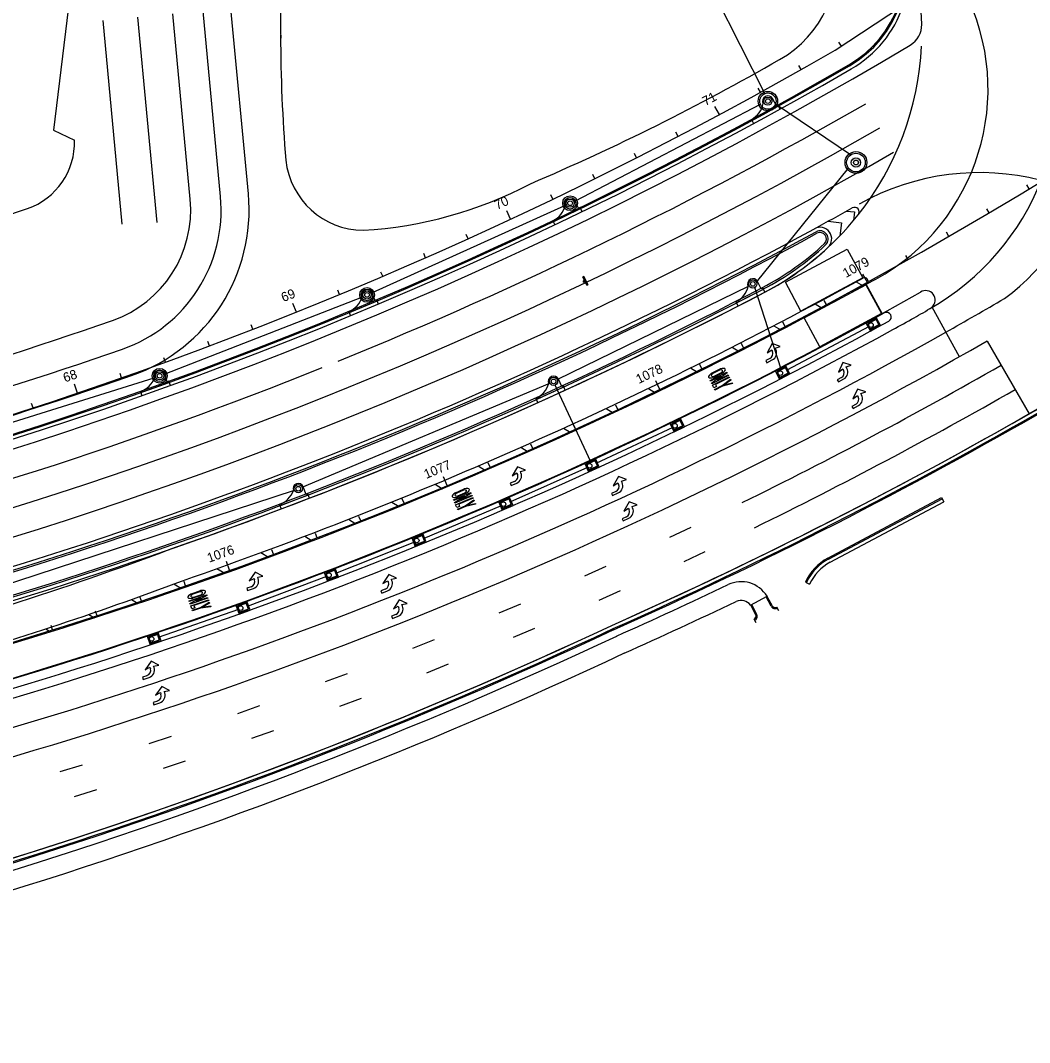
# Model space of a CAD drawing. Extents: x 468143 to 491361, y 1438528 to 1468730.
# Drawn here: x 489702.4 to 490134.6, y 1466592.5 to 1467030.2 of the extents above; entities that cross this region are included whole.
import ezdxf

# ---------------------------------------------------------------- set-up
doc = ezdxf.new("R2010")
doc.units = 0
doc.layers.add('Default', color=7, linetype='Continuous')
doc.layers.add('Xreference_dp', color=7, linetype='Continuous')

# ---------------------------------------------------------------- blocks, each defined once
blk = doc.blocks.new('POINT_DISPLAY')
at = {"layer": 'Default'}
blk.add_line((0, 0), (0, 0), dxfattribs=at)
blk = doc.blocks.new('InltCurb1_35')
at = {"layer": 'Default'}
for p, q in [((2.25, 2), (2.25, 5.5)), ((-10, 2), (-10, 0)), ((-10, 1.5), (3, 1.5)), ((3, 2), (2.25, 2)), ((3, 0), (3, 2))]:
    blk.add_line(p, q, dxfattribs=at)
for radius in [1.75, 1]:
    blk.add_circle((0, 5.5), radius, dxfattribs=at)
for centre, radius, start, end in [((-9.85, 12), 10, 269.1432, 319.4677), ((0, 5.5), 2.25, 0, 180)]:
    blk.add_arc(centre, radius, start, end, dxfattribs=at)
for p in [(-1.75, 5.5), (-1.75, 5.5), (-1.62, 4.84), (-1.6, 6.2), (-1.22, 6.76), (-0.66, 7.12), (0, 7.75), (0, 7.25), (0, 7.25), (0, 5.5), (0, 5.5), (0.7, 7.1), (1.26, 6.72), (1.6, 4.8), (1.62, 6.16), (1.75, 5.5), (1.75, 5.5), (-1.26, 4.28), (-0.7, 3.9), (0, 3.75), (0, 3.75), (0, 0), (0, 0), (0.66, 3.88), (1.22, 4.24)]:
    blk.add_blockref('POINT_DISPLAY', p, dxfattribs=at)
blk = doc.blocks.new('InltCurb7_40')
at = {"layer": 'Default'}
for p, q in [((2.5, 4), (-2.5, 4)), ((-2.5, 4), (-2.5, 0)), ((2.5, 3.25), (-2.5, 3.25)), ((-2.5, 0.75), (2.5, 0.75)), ((-2.5, 0), (2.5, 0)), ((2.5, 0), (2.5, 4))]:
    blk.add_line(p, q, dxfattribs=at)
blk.add_lwpolyline([(-2, 0.5), (2, 0.5), (2, 3.5), (-2, 3.5)], close=True, dxfattribs=at)
blk.add_circle((-1.04, 2.19), 1, dxfattribs=at)
for p in [(-2, 3.5), (-2, 2), (-2, 2), (-2, 0.5), (0, 4), (0, 3.5), (0, 3.5), (0, 2), (0, 2), (0, 0.5), (0, 0.5), (0, 0), (0, 0), (2, 3.5), (2, 2), (2, 2), (2, 0.5)]:
    blk.add_blockref('POINT_DISPLAY', p, dxfattribs=at)
blk = doc.blocks.new('MHCover2')
at = {"layer": 'Default'}
for radius in [2, 1.06, 1]:
    blk.add_circle((0, 0), radius, dxfattribs=at)
for p in [(-2, 0), (-2, 0), (-1.83, 0.81), (-1.39, 1.43), (-0.75, 1.85), (0, 2.5), (0, 2), (0, 2), (0, 0), (0, 0), (0, 0), (0.81, 1.83), (1.43, 1.39), (1.85, 0.75), (2, 0), (2, 0), (-1.85, -0.75), (-1.43, -1.39), (-0.81, -1.83), (0, -2), (0, -2), (0, -2.5), (0.75, -1.85), (1.39, -1.43), (1.83, -0.81)]:
    blk.add_blockref('POINT_DISPLAY', p, dxfattribs=at)
blk = doc.blocks.new('JBottom80Dia')
at = {"layer": 'Default'}
for radius in [4.67, 4, 4]:
    blk.add_circle((0, 0), radius, dxfattribs=at)
for p in [(-3.66, 1.61), (-2.79, 2.87), (-1.5, 3.71), (0, 4), (0, 4), (0, 4), (0, 0), (0, 0), (0, 0), (1.61, 3.66), (2.87, 2.79), (3.71, 1.5), (4, 0), (4, 0), (-4, 0), (-4, 0), (-3.71, -1.5), (-2.87, -2.79), (-1.61, -3.66), (0, -4), (0, -4), (0, -4), (1.5, -3.71), (2.79, -2.87), (3.66, -1.61)]:
    blk.add_blockref('POINT_DISPLAY', p, dxfattribs=at)
blk = doc.blocks.new('JBottom50Dia')
at = {"layer": 'Default'}
for radius in [3.17, 2.5, 2.5]:
    blk.add_circle((0, 0), radius, dxfattribs=at)
for p in [(-2.29, 1.01), (-1.74, 1.79), (-0.94, 2.32), (0, 2.5), (0, 2.5), (0, 2.5), (0, 0), (0, 0), (0, 0), (1.01, 2.29), (1.79, 1.74), (2.32, 0.94), (2.5, 0), (2.5, 0), (-2.5, 0), (-2.5, 0), (-2.32, -0.94), (-1.79, -1.74), (-1.01, -2.29), (0, -2.5), (0, -2.5), (0, -2.5), (0.94, -2.32), (1.74, -1.79), (2.29, -1.01)]:
    blk.add_blockref('POINT_DISPLAY', p, dxfattribs=at)
blk = doc.blocks.new('JBottom70Dia')
at = {"layer": 'Default'}
for radius in [4.17, 3.5, 3.5]:
    blk.add_circle((0, 0), radius, dxfattribs=at)
for p in [(-3.5, 0), (-3.5, 0), (-3.2, 1.41), (-2.44, 2.51), (-1.32, 3.24), (0, 3.5), (0, 3.5), (0, 3.5), (0, 0), (0, 0), (0, 0), (1.41, 3.2), (2.51, 2.44), (3.24, 1.32), (-3.24, -1.32), (-2.51, -2.44), (-1.41, -3.2), (0, -3.5), (0, -3.5), (0, -3.5), (1.32, -3.24), (2.44, -2.51), (3.2, -1.41), (3.5, 0), (3.5, 0)]:
    blk.add_blockref('POINT_DISPLAY', p, dxfattribs=at)
blk = doc.blocks.new('DALeftTurn_1')
at = {"layer": 'Default'}
for points in [[(5.67, 3.17), (2, 0.5), (4.33, 0.83), (4.33, 0.17)], [(6, 0.17), (6, 0.83), (8.25, 0.5), (5.67, 3.17)], [(2, -2.17), (0, -2.17), (0, -3.17), (2.67, -3.17)]]:
    blk.add_lwpolyline(points, dxfattribs=at)
for centre, radius in [((2, 0.17), 2.33), ((2.67, 0.17), 3.33)]:
    blk.add_arc(centre, radius, 270, 0, dxfattribs=at)
blk = doc.blocks.new('TG')
at = {"layer": 'Default'}
for p, q in [((0.048, -0.011), (-0.048, -0.011)), ((-0.048, -0.011), (-0.048, -0.023)), ((-0.048, -0.023), (0.048, -0.023)), ((0.048, -0.023), (0.048, -0.011))]:
    blk.add_line(p, q, dxfattribs=at)
blk.add_lwpolyline([(-0.048, -0.011), (0.048, -0.011), (0.048, -0.023), (-0.048, -0.023)], close=True, dxfattribs=at)
for start, end in [(0, 180), (180, 0)]:
    blk.add_arc((0, 0), 0.00607, start, end, dxfattribs=at)
blk = doc.blocks.new('ONLY_5')
at = {"layer": 'Default'}
for p, q in [((1.94, 3.96), (6.06, 3.96)), ((6.06, 1.96), (1.94, 1.96)), ((5.6, 3.63), (2.4, 3.63)), ((2.4, 2.29), (5.6, 2.29))]:
    blk.add_line(p, q, dxfattribs=at)
for points in [[(0, -0.12), (0, 0.21), (5, 1.13), (0, 1.13), (0, 1.46), (8, 1.46), (8, 1.13), (2.9, 0.21), (8, 0.21), (8, -0.12), (0, -0.12)], [(1.33, -2.12), (0, -2.12), (0, -0.79), (8, -0.79), (8, -1.12), (1.33, -1.12), (1.33, -2.12)], [(8, -3.96), (3.67, -3.12), (0, -3.12), (0, -2.79), (3.67, -2.79), (8, -1.96), (8, -2.3), (4.57, -2.96), (8, -3.62), (8, -3.96)]]:
    blk.add_lwpolyline(points, dxfattribs=at)
for major_axis, ratio, start_param, end_param in [((4, 0), 0.291667, 2.111896, 4.171289), ((2.67, 0), 0.3125, 2.214297, 4.068888), ((2.67, 0), 0.3125, 5.35589, 7.210481), ((4, 0), 0.291667, 5.253489, 7.312882)]:
    blk.add_ellipse((4, 2.96), major_axis=major_axis, ratio=ratio, start_param=start_param, end_param=end_param, dxfattribs=at)

msp = doc.modelspace()

# ---------------------------------------------------------------- linework, layer by layer
at = {"layer": 'Xreference_dp'}
for p, q in [((490051.34, 1467017.44), (490235.32, 1467139.02)), ((490021.16, 1466998.87), (489996.32, 1467047.97)), ((489800.04, 1466955.98), (489792.58, 1467035.34)), ((489800.04, 1466955.98), (489792.58, 1467035.34)), ((489761.02, 1466943.73), (489752.75, 1467031.6)), ((489761.02, 1466943.73), (489752.75, 1467031.6)), ((489775.15, 1466953.64), (489767.69, 1467033)), ((489775.15, 1466953.64), (489767.69, 1467033)), ((489788.09, 1466954.85), (489780.63, 1467034.22)), ((489788.09, 1466954.85), (489780.63, 1467034.22)), ((489746.02, 1466942.95), (489737.82, 1467030.19)), ((489746.02, 1466942.95), (489737.82, 1467030.19)), ((490054.07, 1467019.24), (490052.97, 1467020.91)), ((490036.81, 1467009.15), (490035.83, 1467010.89)), ((490019.34, 1466999.42), (490018.37, 1467001.17)), ((489940.15, 1466952.91), (490019.29, 1466994.29)), ((490001.76, 1466989.88), (489999.87, 1466993.4)), ((490057.89, 1466972.6), (490025.74, 1466994.28)), ((489984.08, 1466980.53), (489983.15, 1466982.31)), ((489966.3, 1466971.38), (489965.39, 1466973.16)), ((490017.64, 1466918.18), (490057, 1466967.01)), ((489948.41, 1466962.43), (489947.53, 1466964.22)), ((490134.43, 1466958.1), (490133.4, 1466959.81)), ((489930.43, 1466953.67), (489929.57, 1466955.47)), ((489853.18, 1466913.64), (489935.54, 1466950.97)), ((489912.36, 1466945.11), (489910.66, 1466948.73)), ((490117.27, 1466947.83), (490116.25, 1466949.55)), ((490100, 1466937.74), (490099, 1466939.47)), ((489894.19, 1466936.75), (489893.36, 1466938.57)), ((489875.93, 1466928.59), (489875.12, 1466930.42)), ((490082.63, 1466927.83), (490081.65, 1466929.57)), ((489857.58, 1466920.63), (489856.79, 1466922.47)), ((490065.16, 1466918.1), (490063.23, 1466921.61)), ((490060.39, 1466918.34), (490063.35, 1466916.54)), ((490071.48, 1466904.74), (490064.62, 1466917.23)), ((489839.14, 1466912.88), (489838.38, 1466914.73)), ((489932.34, 1466876.39), (490014.53, 1466916.57)), ((490028.14, 1466880.81), (490016.89, 1466915.82)), ((489764.41, 1466878.88), (489848.57, 1466911.7)), ((489820.62, 1466905.33), (489819.13, 1466909.04)), ((490042.77, 1466908.82), (490045.76, 1466907.01)), ((490047.58, 1466908.56), (490046.64, 1466910.32)), ((490104.53, 1466886.1), (490092.83, 1466907.41)), ((489802.02, 1466897.98), (489801.3, 1466899.85)), ((490025.06, 1466899.49), (490028.06, 1466897.67)), ((490029.91, 1466899.2), (490028.98, 1466900.97)), ((490065.9, 1466899.13), (490030.61, 1466880.4)), ((489783.34, 1466890.84), (489782.64, 1466892.71)), ((490012.13, 1466890.02), (490011.23, 1466891.81)), ((490116.41, 1466892.92), (490134.43, 1466861.77)), ((490007.25, 1466890.35), (490010.27, 1466888.51)), ((489764.58, 1466883.9), (489763.9, 1466885.78)), ((489994.27, 1466881.04), (489993.38, 1466882.83)), ((489745.75, 1466877.17), (489745.09, 1466879.06)), ((489989.34, 1466881.39), (489992.38, 1466879.54)), ((489618.9, 1466833.06), (489759.7, 1466877.2)), ((489726.84, 1466870.65), (489725.56, 1466874.44)), ((489823.05, 1466830.32), (489929.15, 1466874.93)), ((489946.73, 1466841.22), (489931.47, 1466874.07)), ((489976.31, 1466872.24), (489974.57, 1466875.84)), ((489971.34, 1466872.62), (489974.4, 1466870.76)), ((489707.86, 1466864.34), (489707.24, 1466866.24)), ((489958.26, 1466863.63), (489957.4, 1466865.44)), ((489953.25, 1466864.04), (489956.33, 1466862.17)), ((489935.06, 1466855.65), (489938.17, 1466853.77)), ((489940.12, 1466855.21), (489939.28, 1466857.02)), ((489949.01, 1466840.58), (489981.91, 1466856.06)), ((489916.79, 1466847.45), (489919.92, 1466845.55)), ((489921.89, 1466846.97), (489921.07, 1466848.8)), ((489898.43, 1466839.44), (489901.58, 1466837.53)), ((489903.57, 1466838.94), (489902.78, 1466840.77)), ((489912.13, 1466824.11), (489945.37, 1466838.91)), ((489885.18, 1466831.09), (489883.63, 1466834.78)), ((489879.99, 1466831.63), (489883.17, 1466829.7)), ((489644.78, 1466771.71), (489819.77, 1466829.08)), ((489866.7, 1466823.43), (489865.95, 1466825.29)), ((490048.24, 1466799.96), (490096.93, 1466825.87)), ((490048.47, 1466799.52), (490097.16, 1466825.42)), ((490096.93, 1466825.87), (490097.87, 1466824.1)), ((489861.47, 1466824), (489864.67, 1466822.06)), ((489875.03, 1466808.43), (489908.46, 1466822.52)), ((490049.18, 1466798.19), (490097.87, 1466824.1)), ((489842.86, 1466816.58), (489846.09, 1466814.62)), ((489848.15, 1466815.97), (489847.41, 1466817.83)), ((489989.48, 1466813.13), (489980.44, 1466808.86)), ((489824.18, 1466809.35), (489827.43, 1466807.37)), ((489829.51, 1466808.71), (489828.79, 1466810.58)), ((489810.8, 1466801.64), (489810.11, 1466803.51)), ((489837.47, 1466793.55), (489871.3, 1466806.99)), ((489805.42, 1466802.31), (489808.7, 1466800.32)), ((489995.51, 1466802.71), (489986.47, 1466798.43)), ((489786.59, 1466795.47), (489789.9, 1466793.47)), ((489792.02, 1466794.76), (489790.67, 1466798.53)), ((489953.17, 1466796.34), (489944.05, 1466792.26)), ((489773.17, 1466788.09), (489772.51, 1466789.98)), ((489799.66, 1466779.45), (489833.63, 1466792.28)), ((489768.17, 1466788.91), (489771.41, 1466786.95)), ((489959.21, 1466785.9), (489950.09, 1466781.81)), ((490038.57, 1466789.69), (490040.39, 1466788.86)), ((489750.03, 1466782.29), (489752.82, 1466780.6)), ((489754.25, 1466781.61), (489753.61, 1466783.5)), ((490023.86, 1466779.42), (490021.75, 1466783.38)), ((490024.3, 1466779.66), (490022.52, 1466783)), ((489735.26, 1466775.33), (489734.64, 1466777.23)), ((489761.56, 1466766.14), (489795.9, 1466778.09)), ((489916.54, 1466780.29), (489907.33, 1466776.4)), ((490017.27, 1466775.84), (490015.46, 1466779.23)), ((490017.71, 1466776.07), (490015.59, 1466780.05)), ((490027.23, 1466777.4), (490026.34, 1466779.04)), ((489731.76, 1466775.89), (489734.15, 1466774.44)), ((490017.52, 1466772.22), (490016.66, 1466773.81)), ((489713.36, 1466769.69), (489715.38, 1466768.46)), ((489716.21, 1466769.25), (489715.61, 1466771.16)), ((489922.58, 1466769.83), (489913.38, 1466765.92)), ((489879.58, 1466764.99), (489870.29, 1466761.29)), ((489885.64, 1466754.5), (489876.35, 1466750.78)), ((489842.32, 1466750.45), (489832.96, 1466746.93)), ((489848.39, 1466739.92), (489839.03, 1466736.39)), ((489804.77, 1466736.66), (489795.34, 1466733.33)), ((489810.86, 1466726.09), (489801.43, 1466722.75)), ((489766.95, 1466723.64), (489757.45, 1466720.51)), ((489728.87, 1466711.39), (489719.31, 1466708.45)), ((489773.05, 1466713.03), (489763.56, 1466709.88)), ((489734.99, 1466700.73), (489725.44, 1466697.78))]:
    msp.add_line(p, q, dxfattribs=at)
for points in [[(489714.61, 1467045.17), (489723.62, 1467040.84), (489716.58, 1466983.27)], [(489714.61, 1467045.17), (489723.62, 1467040.84), (489716.58, 1466983.27)], [(489716.58, 1466983.27), (489725.6, 1466978.94)], [(489716.58, 1466983.27), (489725.6, 1466978.94)], [(490056.22, 1466948.58), (490059.62, 1466948.18), (490059.18, 1466944.47)], [(490048.3, 1466944.21), (490054.02, 1466943.53), (490053.36, 1466937.98)], [(490015.11, 1466779.79), (490022.17, 1466783.61)]]:
    msp.add_lwpolyline(points, dxfattribs=at)
for points in [[(490036.69, 1466905.77), (490030.06, 1466918.1), (490056.48, 1466932.31), (490063.11, 1466919.98)], [(490044.72, 1466890.46), (490038.08, 1466902.79), (490064.5, 1466917.01), (490071.13, 1466904.68)]]:
    msp.add_lwpolyline(points, close=True, dxfattribs=at)
for centre, radius, start, end in [((490138.67, 1467029.15), 324.85, 164.6707, 181.156), ((490138.67, 1467029.15), 324.85, 164.6707, 181.156), ((490033.18, 1467052.73), 48, 299.99, 21.6611), ((490033.18, 1467052.73), 48.5, 299.99, 21.6611), ((490033.18, 1467052.73), 50, 299.99, 21.6611), ((489962.81, 1467025.06), 125.62, 1.5824, 21.6611), ((489145.02, 1468591.69), 1909.86, 245.36712, 306.9274), ((490004.74, 1467054.47), 46.92, 299.021, 13.5238), ((490004.74, 1467054.47), 46.92, 299.021, 13.5238), ((490023.78, 1467000.79), 93, 296.0457, 24.205), ((490037.59, 1467002.13), 109.71, 299.595, 17.295), ((490078.39, 1467028.25), 10, 300.8369, 1.5824), ((490062.06, 1466993.34), 102.87, 306.956, 19.9385), ((490507.48, 1467026.01), 693.65, 180.18112, 184.60572), ((490507.48, 1467026.01), 693.65, 180.18112, 184.60572), ((489143.9, 1468591.41), 1816.82, 245.36787, 299.96455), ((489145.02, 1468591.69), 1830.86, 272.37289, 300.83686), ((489962.81, 1467025.06), 125.62, 321.5459, 357.3247), ((489530.42, 1467877.42), 996.77, 293.05774, 299.91346), ((489530.42, 1467877.42), 996.77, 293.05774, 299.91346), ((489145.02, 1468591.69), 1824.86, 271.73266, 299.99002), ((489145.02, 1468591.69), 1825.36, 271.73266, 299.99002), ((489145.02, 1468591.69), 1826.86, 271.73266, 299.99002), ((489145.02, 1468591.69), 1842.86, 292.10506, 299.92655), ((489145.02, 1468591.69), 1854.86, 276.09654, 299.92655), ((489695.62, 1466977.98), 30, 289.0838, 1.8298), ((489695.62, 1466977.98), 30, 289.0838, 1.8298), ((489145.02, 1468591.69), 1866.86, 276.09086, 299.92655), ((489849.58, 1466974.07), 33.72, 186.3956, 269.3897), ((489849.58, 1466974.07), 33.72, 186.3956, 269.3897), ((490113.32, 1466858.91), 106.12, 32.7747, 119.1969), ((489838.84, 1467116.21), 176.17, 273.3788, 297.7303), ((489838.84, 1467116.21), 176.17, 273.3788, 297.7303), ((489725.37, 1466948.96), 50, 289.2192, 5.3709), ((489725.37, 1466948.96), 50, 289.2192, 5.3709), ((489725.37, 1466948.96), 63, 289.2192, 5.3709), ((489725.37, 1466948.96), 63, 289.2192, 5.3709), ((489725.37, 1466948.96), 75, 289.2192, 5.3709), ((489725.37, 1466948.96), 75, 289.2192, 5.3709), ((489124.19, 1468629.67), 1777.74, 288.74085, 289.0838), ((489124.19, 1468629.67), 1777.74, 288.74085, 289.0838), ((489145.02, 1468591.69), 1878.86, 298.53195, 299.09536), ((490059.62, 1466948.18), 2, 321.5459, 119.0954), ((489962.81, 1467025.06), 125.62, 297.5646, 321.5459), ((489145.02, 1468591.69), 1878.86, 283.80177, 298.53195), ((489145.02, 1468591.69), 1878.86, 283.80177, 298.53195), ((489145.02, 1468591.69), 1880.36, 283.80626, 298.53195), ((489145.02, 1468591.69), 1881.11, 283.80851, 298.53195), ((490044.85, 1466936.63), 5, 313.0225, 118.5319), ((490044.85, 1466936.63), 3.5, 313.0225, 118.5319), ((490044.85, 1466936.63), 3.5, 313.0225, 118.5319), ((490044.85, 1466936.63), 2.75, 313.0225, 118.5319), ((489964.34, 1467022.9), 120.75, 297.5761, 313.0225), ((489964.34, 1467022.9), 121.5, 297.5761, 313.0225), ((489964.34, 1467022.9), 123, 297.5761, 313.0225), ((489145.02, 1468591.69), 1910.36, 283.79147, 298.7751), ((489145.02, 1468591.69), 1907.36, 289.18461, 298.7751), ((490063.93, 1466918.56), 1.5, 297.505, 120.0452), ((489145.02, 1468591.69), 1890.61, 283.30727, 297.57606), ((489145.02, 1468591.69), 1891.36, 283.30727, 297.57606), ((489145.02, 1468591.69), 1892.86, 283.30727, 297.57606), ((489145.02, 1468591.69), 1924.61, 283.79147, 299.33378), ((489145.02, 1468591.69), 1892.86, 289.17951, 297.5646), ((490090.13, 1466910.47), 4.07, 311.4264, 123.5928), ((489145.02, 1468591.69), 1944.86, 299.36432, 300.21967), ((489145.02, 1468591.69), 1924.86, 283.79147, 298.80179), ((490073.35, 1466903.2), 2, 298.8018, 118.8018), ((490033.27, 1466999.89), 110, 298.1198, 302.7809), ((489139.18, 1468630.45), 1830.74, 276.12591, 289.21916), ((489139.18, 1468630.45), 1830.74, 276.12591, 289.21916), ((489145.02, 1468591.69), 1928.86, 283.80177, 298.80179), ((489145.02, 1468591.69), 1932.86, 298.79546, 299.10288), ((489145.02, 1468591.69), 1932.86, 283.80177, 298.79546), ((489145.02, 1468591.69), 1944.86, 285.35186, 299.36432), ((489145.02, 1468591.69), 1956.86, 284.31651, 299.76158), ((489139.28, 1468630.01), 1843.29, 276.1243, 289.22077), ((489139.28, 1468630.01), 1843.29, 276.1243, 289.22077), ((489145.02, 1468591.69), 1968.86, 296.11138, 299.76336), ((489139.17, 1468630.52), 1855.81, 276.12615, 289.21892), ((489139.17, 1468630.52), 1855.81, 276.12615, 289.21892), ((489145.02, 1468591.69), 1842.86, 283.80836, 291.87736), ((489145.02, 1468591.69), 1992.86, 294.00179, 300.31286), ((489145.02, 1468591.69), 1980.86, 296.11138, 299.76512), ((489145.02, 1468591.69), 1992.86, 294.00179, 300.03817), ((489145.02, 1468591.69), 1994.36, 294.00179, 300.03817), ((489145.02, 1468591.69), 1994.86, 294.00179, 300.03817), ((489217.57, 1468271.43), 1566.97, 285.15473, 290.52137), ((490058.57, 1466780.54), 22, 118.0164, 155.4077), ((490058.57, 1466780.54), 21.5, 118.0164, 155.4077), ((490058.57, 1466780.54), 20, 118.0164, 155.4077), ((489217.57, 1468271.43), 1581.47, 286.19088, 290.51522), ((490011.05, 1466776.88), 13, 31.1842, 115.5103), ((489145.02, 1468591.69), 1997.86, 294.00179, 295.51033), ((489145.02, 1468591.69), 2005.86, 294.00179, 295.51033), ((490011.05, 1466776.88), 5, 35.644, 115.5103), ((490011.05, 1466776.88), 13, 28.0993, 31.1842), ((490011.05, 1466776.88), 5, 28.0993, 35.644), ((490025.63, 1466780.36), 2, 208.0993, 298.4071), ((490025.63, 1466780.36), 1.5, 208.0993, 298.4071), ((490015.95, 1466775.13), 1.5, 298.4071, 28.0993), ((490015.95, 1466775.13), 2, 298.4071, 28.0993), ((489097.74, 1468600.78), 2020.78, 279.09522, 295.12185), ((489097.74, 1468600.78), 2022.28, 279.09522, 295.12185), ((489097.74, 1468600.78), 2022.78, 279.09522, 295.12185), ((489097.69, 1468600.77), 2020.79, 279.11452, 295.12334), ((489097.74, 1468600.78), 2025.78, 279.09355, 295.12185), ((489097.74, 1468600.78), 2033.78, 279.09089, 295.12185)]:
    msp.add_arc(centre, radius, start, end, dxfattribs=at)

# ---------------------------------------------------------------- block references
for name, p, rotation in [('JBottom70Dia', (490022.52, 1466995.65), 112.84890317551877), ('InltCurb1_35', (490025.17, 1466990.83), 28.848903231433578), ('JBottom80Dia', (490060.24, 1466969.36), 35.99657665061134), ('MHCover2', (490060.24, 1466969.36), 37.840414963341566), ('InltCurb1_35', (489940.24, 1466946.99), 25.851000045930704), ('JBottom50Dia', (489937.84, 1466951.94), 112.84890317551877), ('JBottom50Dia', (489850.88, 1466912.67), 112.84890317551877), ('InltCurb1_35', (490018.61, 1466912.49), 27.37879610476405), ('InltCurb1_35', (489853.01, 1466907.6), 22.848903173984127), ('InltCurb7_40', (490068.61, 1466898.33), 28.60869637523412), ('DALeftTurn_1', (490020.62, 1466886.49), 26.071048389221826), ('JBottom50Dia', (489762.05, 1466878.04), 109.64434005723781), ('ONLY_5', (489998.44, 1466874.73), 26.375397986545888), ('InltCurb7_40', (490029.75, 1466877.7), 27.338935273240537), ('DALeftTurn_1', (490051.2, 1466878.17), 29.065881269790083), ('InltCurb1_35', (489763.9, 1466872.86), 19.644340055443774), ('InltCurb1_35', (489933.04, 1466870.66), 24.64729195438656), ('DALeftTurn_1', (490057.46, 1466866.79), 29.065881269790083), ('InltCurb7_40', (489984.58, 1466855.13), 25.8389528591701), ('InltCurb7_40', (489948.03, 1466837.93), 24.638926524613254), ('DALeftTurn_1', (489911.31, 1466834), 22.7075551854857), ('DALeftTurn_1', (489954.71, 1466829.67), 24.667381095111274), ('InltCurb1_35', (489823.37, 1466824.56), 20.8477870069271), ('ONLY_5', (489888.47, 1466823.56), 23.01190478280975), ('InltCurb7_40', (489911.09, 1466821.48), 23.437871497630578), ('DALeftTurn_1', (489959.23, 1466818.82), 24.667381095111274), ('InltCurb7_40', (489873.88, 1466805.84), 21.03892095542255), ('DALeftTurn_1', (489798.64, 1466789.12), 18.632304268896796), ('InltCurb7_40', (489836.32, 1466790.97), 21.03892095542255), ('DALeftTurn_1', (489856.02, 1466787.94), 21.51970491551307), ('ONLY_5', (489775.12, 1466780.33), 18.936653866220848), ('InltCurb7_40', (489798.46, 1466776.89), 19.838919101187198), ('DALeftTurn_1', (489860.54, 1466777.09), 21.51970491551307), ('InltCurb7_40', (489760.31, 1466763.6), 18.638945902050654), ('DALeftTurn_1', (489754.05, 1466751.07), 18.334281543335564), ('DALeftTurn_1', (489758.57, 1466740.22), 18.334281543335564)]:
    msp.add_blockref(name, p, dxfattribs=dict(at, rotation=rotation))
at = {"layer": 'Xreference_dp', "xscale": 39.999999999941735, "yscale": 39.99999999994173, "rotation": 116.55334390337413}
msp.add_blockref('TG', (489943.69, 1466918.42), dxfattribs=at)

# ---------------------------------------------------------------- texts
at = {"layer": 'Xreference_dp'}
for s, rotation, p in [('71', 28.1756, (489995.76, 1466993.47)), ('70', 25.0219, (489906.56, 1466949.03)), ('1079', 28.8018, (490055.97, 1466919.9)), ('69', 21.8683, (489815.06, 1466909.56)), ('1078', 25.8018, (489967.23, 1466874.51)), ('68', 18.7147, (489721.51, 1466875.18)), ('1077', 22.8018, (489876.23, 1466833.84)), ('1076', 19.8018, (489783.23, 1466797.98))]:
    msp.add_text(s, height=4, rotation=rotation, dxfattribs=at).set_placement(p)

doc.saveas('drawing.dxf')
